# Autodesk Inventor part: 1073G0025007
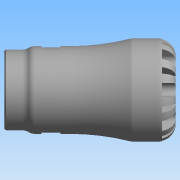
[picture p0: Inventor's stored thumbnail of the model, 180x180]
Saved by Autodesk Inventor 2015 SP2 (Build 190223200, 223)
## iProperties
Created: 2016-12
Part Number: 1073G0025007
Material: Generic
Description: PLASSON FEMALE INTEGRAL BRASS THREAD 25X3/4" G SERIES 1
Document SubType Name: Modeling
Designer: KIM
Density: 1 g/cm^3
Appearance: Default
Author: KIM
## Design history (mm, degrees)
derived "1073G.ipt"
feature "Solid1::1073G.ipt"
tag "TaggingFeature1"
body "Solid1"
other parameters: "d0" = 78, "d1" = 20.16, "d2" = 25, "d3" = 31.25, "d4" = 47, "d6" = 48, "d8" = 39.95, "d13" = 6.3, "d14" = 6.3, "d15" = 0, "d17" = 360 deg, "d19" = 8 deg, "d20" = 0.5, "d21" = 0.5, "d22" = 8 deg, "d24" = 0, "d26" = 360 deg, "d32" = 4.7, "d33" = 4.7, "d39" = 0.72351, "d42" = 24.117, "d43" = 36.66, "d46" = 2.08333, "d47" = 12, "d48" = 22.91115, "d50" = 5.94, "d51" = 0.47, "d54" = 8.75, "d55" = 5.5, "d57" = 12.348, "d58" = 0, "d68" = 360 deg, "d72" = 0.5, "d74" = 0, "d76" = 7.4375, "d_" = 25, "E_" = 47, "H_" = 78, "l_" = 48, "G_" = 24.117, "l_2" = 12, "d9" = 7.875, "d11" = 47, "d12" = 31.25, "d49" = 18
